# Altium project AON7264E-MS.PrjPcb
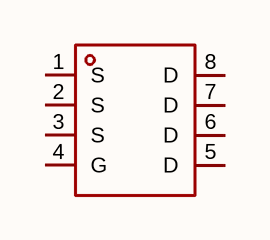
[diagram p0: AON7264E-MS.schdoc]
1 sheet, 1 parts. Net scope: global (net labels, ports and power ports of the same name join across sheets).

## Sheet AON7264E-MS.schdoc
size 127 x 101 mm

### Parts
Q?  aon7264e-ms  [POWERPAK-1212-8_L3.0-W3.0-P0.65-LS3.3-BL]  (value not drawn)

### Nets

Not connected (* = marked no-connect by the designer): Q? 1(S) 2(S) 3(S) 4(G) 5(D) 6(D) 7(D) 8(D)

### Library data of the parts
Q? = aon7264e-ms: 数量:1个N沟道;漏源电压(Vdss):60V;连续漏极电流(Id):-;导通电阻(RDS(on)):12mΩ@10V;耗散功率(Pd):30W;阈值电压(Vgs(th)):1.6V;; Manufacturer: MSKSEMI(美森科); AddInBom: yes; ModelId: 74fc8db97a8d4d328d7f3b4acba39a5e; ModelTransform: 129.921,129.921,0,0,0,0,0,0,0; Number: 1个N沟道; Drain to Source Voltage: 60V; Pd - Power Dissipation: 30W; Gate Threshold Voltage (Vgs(th)): 1.6V; Gate Charge(Qg): 22nC; Input Capacitance(Ciss): 930pF; Reverse Transfer Capacitance (Crss@Vds): 8pF; Type: N沟道; Output Capacitance(Coss): 230pF; Vgs: ±20V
